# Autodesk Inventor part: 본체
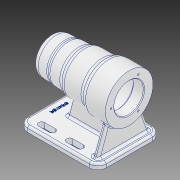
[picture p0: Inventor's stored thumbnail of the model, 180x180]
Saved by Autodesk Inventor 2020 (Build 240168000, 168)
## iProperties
Created: 2021-10
Part Number: 본체
Material: 알루미늄 6061
Document SubType Name: Modeling
Designer: user
Density: 2.7 g/cm^3
Appearance: 알루미늄 - 평지
Mass: 709.168 g
Surface Area: 697.927 cm^2
Volume: 262.655 cm^3
Author: user
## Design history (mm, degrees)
sketch "스케치1"
  geometry: L1 (56, 4)-(56, 17); L2 (56, 17)-(24, 17); L3 (24, 17)-(24, 13); L4 (24, 13)-(-10, 13); L5 (-10, 13)-(-10, 10); L6 (-10, 10)-(-32, 10); L7 (-32, 10)-(-32, 9); L8 (-32, 9)-(-56, 9); L9 (-56, 9)-(-56, -17); L10 (41, 4)-(56, 4); L11 (41, 4)-(41, 4); L12 (38, 7)-(-10, 7); L13 (-13, 4)-(-24.7, 4); L14 (-42.7, 0.5)-(-25, 0.5); L15 (-46.7, -1)-(-43, -1); L16 (-50, -17)-(-50, -9.5); L17 (-47, -6.5)-(-47, -6.5); L18 (-47, -1.3)-(-47, -6.5); L19 (-43, -1)-(-43, 0.2); L20 (-25, 0.5)-(-25, 3.7); L21 (-13, 4)-(-13, 4); L22 (-56, -17)-(41, -17); L23 (41, -17)-(41, 4); A1 r 3 centre (38, 4) between (41, 4) and (38, 7); A2 r 3 centre (-10, 4) between (-10, 7) and (-13, 4); A3 r 0.3 centre (-46.7, -1.3) between (-46.7, -1) and (-47, -1.3); A4 r 0.3 centre (-42.7, 0.2) between (-42.7, 0.5) and (-43, 0.2); A5 r 0.3 centre (-24.7, 3.7) between (-24.7, 4) and (-25, 3.7); A6 r 3 centre (-47, -9.5) between (-47, -6.5) and (-50, -9.5); 11 further points
  constraints: 46 end point, 14 point on line, 12 point on circle, 12 tangent, 10 perpendicular, 6 centre point, 2 equal radius, 2 horizontal, 2 parallel, 1 vertical
  dimensions: "d34" = 34 vertical distance of L22.end L1.end; "d36" = 97 distance of L22.end L9.end; "d37" = 17 distance from line of point (0, 0) L22; "d38" = 41 distance from line of point (0, 0) L23; "d39" = 112 distance between parallel lines of L1 L9; "d40" = 9 distance from line of point (0, 0) L8; "d42" = 50 distance from line of point (0, 0) L16; "d43" = 13.5 distance from line of L12 point (-50, -6.5); "d44" = 3 distance of point (-50, -6.5) L17.end; "d45" = 5.5 distance of point (-47, -1) L17.end; "d46" = 4 distance of point (-47, -1) L15.end; "d47" = 22 distance of L5.end L6.end; "d48" = 34 distance of L3.end L4.end; "d49" = 54 distance of point (41, 7) point (-13, 7); "d50" = 18 distance of point (-43, 0.5) L14.end; "d51" = 7 distance from line of L12 point (0, 0); "d52" = 13 distance from line of point (0, 0) L4; "d53" = 0.5 distance from line of point (0, 0) L14; "d54" = 47 distance from line of point (0, 0) L18; "d55" = 6.5 distance from line of point (0, 0) L17; "d58" = 4 distance from line of point (0, 0) L10; "d59" = 32 distance from line of point (0, 0) L7; "d60" = 1 distance from line of point (0, 0) L15; "d62" = 3 distance from line of L10 point (41, 7); "d63" = 3.5 distance from line of L14 point (-25, 4); "d64" = 10.5 distance from line of L22 point (-50, -6.5) (derived); "d137" = 3 radius of A1; "d138" = 3 radius of A2 (derived); "d139" = 0.3 radius of A3; "d143" = 3 radius of A6; "d145" = 24 horizontal distance of L8.end L6.end (derived); "d146" = 46 horizontal distance of L4.end L8.end (derived); "d147" = 80 horizontal distance of L2.end L8.end (derived); "d149" = 27 distance between parallel lines of L22 L6; "d150" = 26 distance of L9.end L8.end
revolve "회전1" sketch "스케치1" stored, may be unused: angle "d65" = 360 deg
node "작업 평면2"
  node "작업 평면1"
sketch "스케치2"
  geometry: L1 (-56, -45)-(56, -45); L2 (56, -45)-(56, 45); L3 (56, 45)-(-56, 45); L4 (-56, 45)-(-56, -45); 1 further point
  constraints: 8 end point, 2 parallel, 1 horizontal, 1 perpendicular
  dimensions: "d68" = 112 distance of L3.end L2.end; "d69" = 90 distance of L2.end L1.end; "d70" = 56 distance from line of point (0, 0) L4; "d71" = 45 distance from line of point (0, 0) L1
extrude "돌출1" join sketch "스케치2" distance "d72" = 8; taper "d73" = 0 deg
sketch "스케치3"
  geometry: L1 (56, 45)-(-56, 45) reference; L2 (-56, -45)-(56, -45) reference; L3 (56, -45)-(56, 45) reference; L4 (-29, 4)-(40, 4); L5 (40, 4)-(40, -4); L6 (40, -4)-(-29, -4); L7 (-29, -4)-(-29, 4); 1 further point
  constraints: 8 end point, 2 parallel, 1 horizontal, 1 perpendicular
  dimensions: "d79" = 69 distance of L5.end L6.end; "d80" = 8 distance of L4.end L5.end; "d83" = 4 distance from line of point (0, 0) L4; "d87" = 16 distance between parallel lines of L3 L5
extrude "돌출2" join sketch "스케치3" stored distance "d85" = 8; taper "d86" = 0 deg
sketch "스케치4"
  geometry: L1 (-19.409, 37.342)-(-33, 0); L2 (-41, 0)-(49, 0) reference; L3 (27.409, 37.342)-(39.635, 3.751); L4 (39.635, 3.751)-(41, 0); A1 r 34 centre (4, 62) between (-19.409, 37.342) and (27.409, 37.342) reference; 1 further point
  constraints: 6 end point, 3 point on line, 2 point on circle
  dimensions: "d88" = 8 distance of L2.start L1.end; "d89" = 70 deg angle of L2 L1; "d90" = 8 distance of L2.end L4.end; "d91" = 70 deg angle of L2 L3
extrude "돌출3" join sketch "스케치4" distance "d92" = 8; taper "d93" = 0 deg
feature "면 기울기1" dims angle "d95" = 15 deg
sketch "스케치6"
  geometry: L1 (0, 0)-(-26, 0); L2 (0, 0)-(13, 22.517); L3 (0, 0)-(26, 0); C1 r 26 at (0, 0); C2 r 34 at (0, 0) reference; A1 r 26 centre (0, 0) between (13, 22.517) and (-26, 0) reference; 2 further points
  constraints: 6 end point, 2 coincident, 2 horizontal, 2 point on circle, 1 centre point, 1 concentric, 1 equal length
  dimensions: "d103" = 52 diameter of C1; "d104" = 60 deg angle of L3 L2
hole "구멍1" sketch "스케치6" at (13, 22.517) diameter "d96" = 2.459; stored, may be unused: countersink angle "d100" = 90 deg, drill point angle "d102" = 118 deg; dims "d97" = 8, "d98" = 4, "d99" = 2, "d101" = 11
fillet "모깎기1" dims "d108" = 12
sketch "스케치7"
  geometry: L1 (19, -33)-(4, -33); L2 (19, -28.5)-(4, -28.5); L3 (4, -37.5)-(19, -37.5); L4 (-21, -33)-(-36, -33); L5 (-21, -28.5)-(-36, -28.5); L6 (-36, -37.5)-(-21, -37.5); L7 (-56, 33)-(-56, -33) reference; A1 r 4.5 centre (19, -33) between (19, -37.5) and (19, -28.5); A2 r 4.5 centre (4, -33) between (4, -28.5) and (4, -37.5); A3 r 4.5 centre (-21, -33) between (-21, -37.5) and (-21, -28.5); A4 r 4.5 centre (-36, -33) between (-36, -28.5) and (-36, -37.5); 3 further points
  constraints: 16 end point, 8 point on circle, 8 tangent, 4 centre point, 3 parallel, 2 midpoint, 1 horizontal alignment
  dimensions: "d113" = 7.5 distance of point (11.5, -33) L1.end; "d114" = 9 diameter of A2; "d115" = 7.5 distance of point (-28.5, -33) L4.end; "d116" = 9 diameter of A4; "d117" = 20 distance from line of L4.end L7; "d118" = 25 distance of L1.end L4.start; "d119" = 33 vertical distance of L4.end point (0, 0); "d120" = 33 vertical distance of point (11.5, -33) point (0, 0)
extrude "돌출4" cut sketch "스케치7" stored distance "d121" = 8; taper "d122" = 0 deg
fillet "모깎기2" dims "d123" = 3
fillet "모깎기3" dims "d124" = 3
fillet "모깎기7" dims "d128" = 8
fillet "모깎기9" dims "d130" = 8
fillet "모깎기10" dims "d131" = 3
chamfer "모따기1" distance "d132" = 1; stored, may be unused: second distance "d133" = 2, angle "d134" = 45 deg
sketch "스케치8"
  geometry: L1 (-56, 33)-(-56, -33) reference; 2 further points
  constraints: 1 horizontal alignment, 1 other
  dimensions: "d140" = 12 distance from line of L1 point (-44, 0)
extrude "돌출5" join sketch "스케치8" distance "d141" = 0.5; taper "d142" = 0 deg
fillet "모깎기13" dims "d144" = 3
node "솔리드1"
pattern_circular "원형 패턴1" dims angle "d106" = 360 deg
mirror "미러1"
feature "A9D066F2-1C7D-4E18-AEED-F7BC21143FA4" dims "d96" = 2.459, "d97" = 8, "d98" = 4, "d99" = 2, "d100" = 90 deg, "d101" = 11, "d102" = 118 deg
other parameters: "d66" = -17, "sa_0" = 4
